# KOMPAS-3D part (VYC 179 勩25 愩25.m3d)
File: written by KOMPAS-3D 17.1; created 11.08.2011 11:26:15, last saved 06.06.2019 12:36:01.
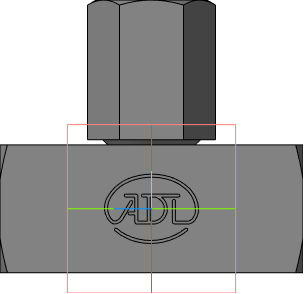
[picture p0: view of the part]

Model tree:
1. Плоскость XY
2. Плоскость ZX
3. Плоскость ZY
4. Ось X
5. Ось Y
6. Ось Z
7. Начало координат
8. Операция без истории:2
